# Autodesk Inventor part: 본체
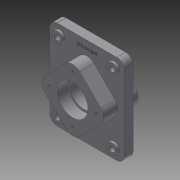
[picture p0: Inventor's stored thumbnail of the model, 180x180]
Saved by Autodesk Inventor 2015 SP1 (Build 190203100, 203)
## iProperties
Created: 2026-07
Part Number: 본체
Material: 일반
Document SubType Name: Modeling
Designer: user
Density: 1 g/cm^3
Appearance: 기본값
Author: user
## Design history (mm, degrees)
sketch "스케치1"
  geometry: L1 (75, 90)-(-75, 90); L2 (-75, 90)-(-75, -90); L3 (-75, -90)-(75, -90); L4 (75, -90)-(75, 90); L5 (75, 90)-(-75, -90); L6 (-75, 90)-(75, -90); L7 (0, -70.711)-(-70.711, 0); L8 (-70.711, 0)-(0, 70.711); L9 (0, 70.711)-(70.711, 0); L10 (70.711, 0)-(0, -70.711); 3 further points
  constraints: 20 end point, 3 midpoint, 2 parallel, 1 coincident, 1 horizontal, 1 perpendicular, 1 vertical alignment, 9 other
  dimensions: "d0" = 150 distance of L3.end L2.end; "d1" = 180 distance of L2.end L1.end; "d2" = 100 distance between parallel lines of L7 L9
extrude "돌출1" new body sketch "스케치1" stored distance "d3" = 18; taper "d4" = 0 deg
extrude "돌출2" join sketch "스케치1" distance "d5" = 32; taper "d7" = 0 deg; dims "d6" = 38, "d8" = 0
fillet "모깎기1" dims "d9" = 20
fillet "모깎기2" dims "d10" = 20
fillet "모깎기3" dims "d11" = 15
sketch "스케치2"
  geometry: L1 (-75, 75)-(-75, -75) reference; L2 (-60, -90)-(60, -90) reference; C1 r 11 at (-55, -70); 1 further point
  constraints: 1 centre point
  dimensions: "d12" = 22 diameter of C1; "d13" = 20 distance from line of C1.centre L1; "d14" = 20 distance from line of L2 C1.centre
extrude "돌출3" join sketch "스케치2" distance "d15" = 5; taper "d16" = 0 deg
hole "구멍1" diameter "d19" = 11; stored, may be unused: countersink angle "d23" = 90 deg, drill point angle "d25" = 118 deg; dims "d17" = 10, "d18" = 10, "d20" = 6, "d21" = 4, "d22" = 2, "d24" = 8
sketch "스케치3"
  geometry: C1 r 31 at (0, 0); 1 further point
  constraints: 1 centre point, 1 coincident
  dimensions: "d32" = 62 diameter of C1
extrude "돌출4" cut sketch "스케치3" distance "d33" = 22; taper "d34" = 0 deg
hole "구멍2" diameter "d37" = 54; stored, may be unused: countersink angle "d41" = 90 deg, drill point angle "d43" = 118 deg; dims "d35" = 10, "d36" = 10, "d38" = 6, "d39" = 4, "d40" = 2, "d42" = 8
hole "구멍3" diameter "d46" = 62; stored, may be unused: countersink angle "d50" = 90 deg, drill point angle "d52" = 0 deg; dims "d44" = 10, "d45" = 10, "d47" = 6, "d48" = 4, "d49" = 2, "d51" = 22
sketch "스케치4"
  geometry: L1 (0, 0)-(0, 48)
  constraints: 2 end point, 1 vertical
  dimensions: "d53" = 48 distance of L1.start L1.end
hole "구멍4" sketch "스케치4" at (0, 48) diameter "d54" = 4.917; stored, may be unused: countersink angle "d58" = 90 deg, drill point angle "d60" = 118 deg; dims "d55" = 10, "d56" = 4, "d57" = 2, "d59" = 13
sketch "스케치5"
  geometry: L1 (0, 0)-(0, -48)
  constraints: 2 end point, 1 vertical
  dimensions: "d64" = 48 distance of L1.start L1.end
hole "구멍5" sketch "스케치5" at (0, -48) diameter "d65" = 4.917; stored, may be unused: countersink angle "d69" = 90 deg, drill point angle "d71" = 118 deg; dims "d66" = 10, "d67" = 4, "d68" = 2, "d70" = 13
sketch "스케치6"
  geometry: L1 (60, 90)-(-60, 90) reference; 2 further points
  constraints: 1 vertical alignment, 1 other
  dimensions: "d75" = 15 distance from line of point (0, 75) L1
feature "엠보싱1" sketch "스케치6" dims "d76" = 0.5, "d77" = 0
node "솔리드1"
pattern_linear "직사각형 패턴1"
pattern_circular "원형 패턴1" dims angle "d62" = 360 deg
pattern_circular "원형 패턴2" dims angle "d73" = 360 deg
